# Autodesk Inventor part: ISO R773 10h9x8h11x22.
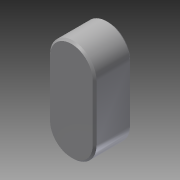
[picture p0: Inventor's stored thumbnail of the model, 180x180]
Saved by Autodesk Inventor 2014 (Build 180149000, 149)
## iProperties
Created: 2001-01
Part Number: ISO R773 10h9x8h11x22.
Material: Steel, Mild
Description: Key 10h9x8h11x22 ISO R773-A.
Document SubType Name: Modeling
Standard: ISO R773
Density: 7.86 g/cm^3
Appearance: Steel
ProtocolID: P00020918112145677
Protocol: P00020918112145677<@PID>[Version]<@EL>Version=2.2<@EL>[Calc]<@EL>ScnVisible=0<@EL>WizardMode=2<@EL>Optim=1<@EL>CalcName=KEY<@EL>[Synchronize]<@EL>ChangedVars=<@
Control State: 0
Master: False
Checked Out: False
Shininess: 20.0
Length Units: 11269
Angle Units: 11279
Time Units: 11290
Mass Units: 11283
Length Display Precision: 3
Angle Display Precision: 2
BOM1: Key Form A
BOM2: 10h9x8h11x22
BOM3: ISO R773
Density: 7.86
Volumn: 6.598322712661924
Area: 23.227147879536034
PropertySet Name: Model Information
Author: PaulN
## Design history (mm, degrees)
node "WorkPlane2"
sketch "Sketch2"
  geometry: L1 (-5, 5)-(-5, 17); L2 (5, 5)-(5, 17); L3 (0, -4.4)-(0, 26.4) reference; L4 (-7, 0)-(7, 0) reference; A1 r 5 centre (0, 5) between (-5, 5) and (5, 5); A2 r 5 centre (0, 17) between (5, 17) and (-5, 17)
  constraints: 4 end point, 4 point on circle, 4 tangent, 2 centre point, 2 vertical
  dimensions: "d2" = 12 distance of L2.start L2.end (= -prf_b + prf_l); "d7" = 5 distance between parallel lines of L3 L1 (= 0.5 x prf_b); "d8" = 10 distance between parallel lines of L2 L1 (= prf_b); "d9" = 5 distance from line of A1.centre L4 (= 0.5 x prf_b)
extrude "ExtrusionBlind1" new body sketch "Sketch2" distance "d3" = 8 (= prf_h); taper "d4" = 0 deg
chamfer "Chamfer2" distance "d14" = 0.4 (= prf_r); stored, may be unused: second distance "d15" = 0.4 (= prf_r), angle "d19" = 45 deg
body "Solid1"
other parameters: "prf_t1" = 5 [user parameter; used in 1 equation term], "prf_b" = 10 [user parameter; used in 4 equation terms], "prf_h" = 8 [user parameter; used in 1 equation term], "prf_l" = 22 [user parameter; used in 1 equation term], "prf_r" = 0.4 [user parameter; used in 2 equation terms], "d0" = -5 (computed from prf_t1), "d1" = 29 (derived), "prf_d" = 35 [user parameter], "msp_alfa" = 360 deg (computed from prf_pocper) [user parameter]
